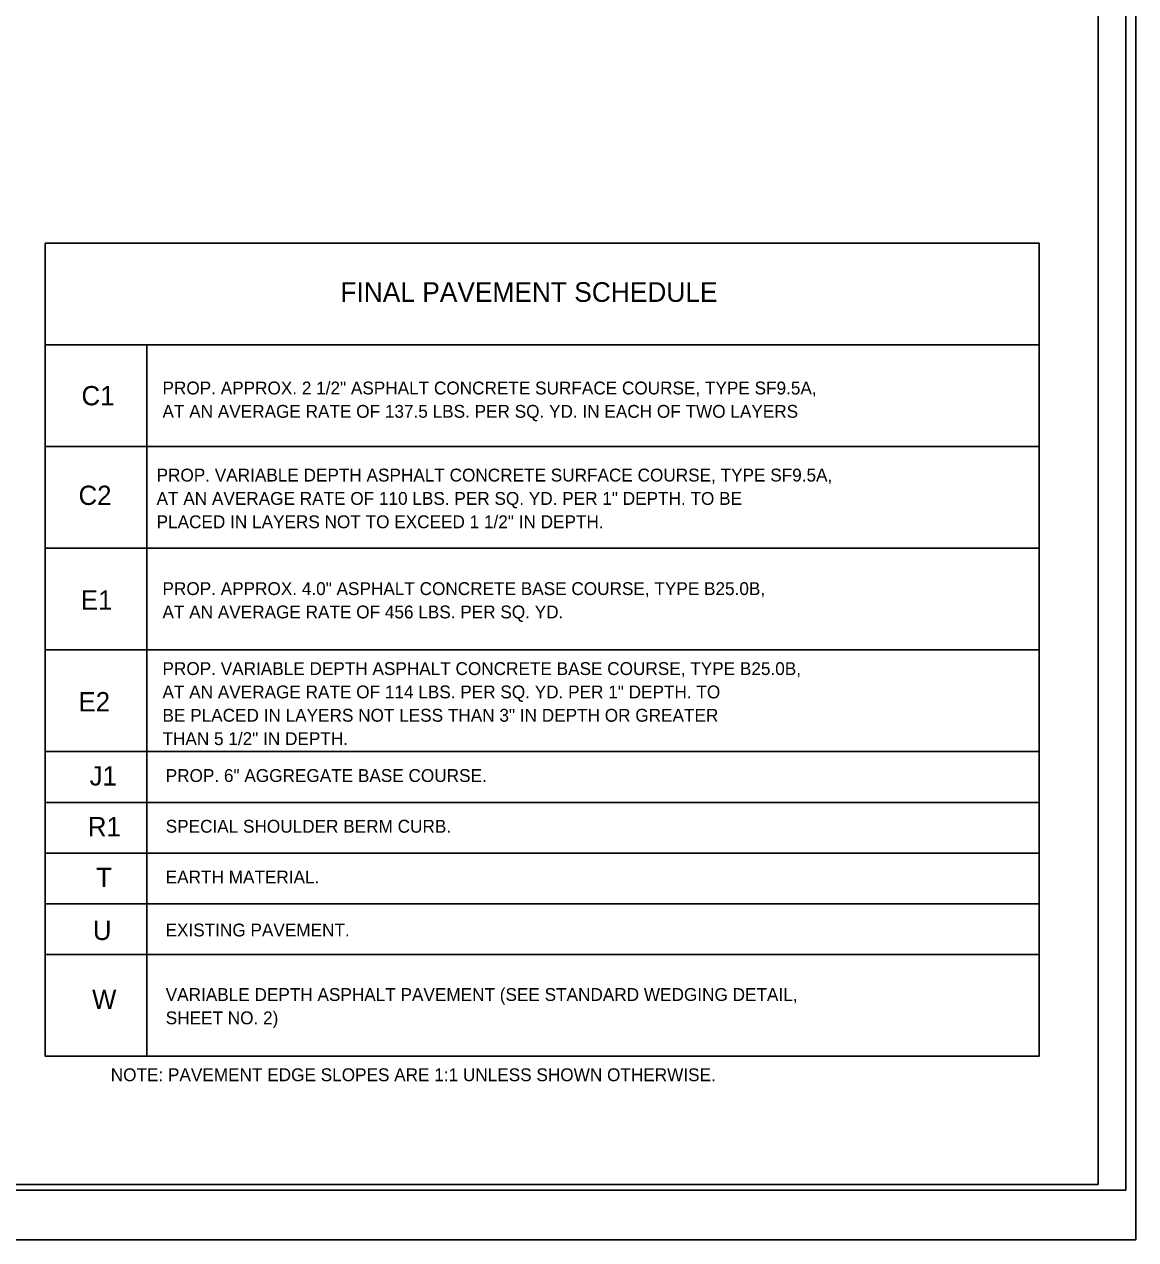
# Model space of a CAD drawing. Extents: x 1542177 to 1542464, y 45134 to 45344.
# Drawn here: x 1542320.47 to 1542360.73, y 45240.62 to 45284.62 of the extents above; entities that cross this region are included whole.
import ezdxf

# ---------------------------------------------------------------- set-up
doc = ezdxf.new("R2010")
doc.units = 0
for name, color, linetype in [('Default', 7, 'Continuous'), ('Sheet Cutting Line CELL', 7, 'Continuous'), ('Sheet Plot Border Inside CELL', 7, 'Continuous'), ('Sheet Plot Border Outside CELL', 7, 'Continuous'), ('Sheet Typical CELL', 7, 'Continuous')]:
    doc.layers.add(name, color=color, linetype=linetype)

msp = doc.modelspace()

# ---------------------------------------------------------------- linework, layer by layer
at = {"layer": 'Default'}
for p, q in [((1542324.908, 45249.102), (1542324.908, 45258.286)), ((1542321.274, 45248.12), (1542321.274, 45248.12))]:
    msp.add_line(p, q, dxfattribs=at)
for points in [[(1542321.226, 45276.696), (1542357.227, 45276.696), (1542357.227, 45273.014), (1542321.226, 45273.014)], [(1542321.226, 45258.286), (1542357.226, 45258.286), (1542357.226, 45256.449), (1542324.908, 45256.449), (1542321.226, 45256.449)], [(1542321.226, 45256.449), (1542357.226, 45256.449), (1542357.226, 45254.612), (1542324.908, 45254.612), (1542321.226, 45254.612)], [(1542321.226, 45254.612), (1542357.226, 45254.612), (1542357.226, 45252.775), (1542324.908, 45252.775), (1542321.226, 45252.775)], [(1542321.226, 45252.775), (1542357.226, 45252.775), (1542357.226, 45250.938), (1542324.908, 45250.938), (1542321.226, 45250.938)]]:
    msp.add_lwpolyline(points, close=True, dxfattribs=at)
for points in [[(1542324.908, 45269.331), (1542321.226, 45269.331), (1542321.226, 45273.014), (1542357.226, 45273.014), (1542357.226, 45269.331), (1542324.908, 45269.331), (1542324.908, 45273.014)], [(1542324.908, 45265.65), (1542321.226, 45265.65), (1542321.226, 45269.331), (1542357.226, 45269.331), (1542357.226, 45265.65), (1542324.908, 45265.65), (1542324.908, 45269.331)], [(1542324.908, 45261.968), (1542321.226, 45261.968), (1542321.226, 45265.65), (1542357.226, 45265.65), (1542357.226, 45261.968), (1542324.908, 45261.968), (1542324.908, 45265.65)], [(1542324.908, 45258.286), (1542321.226, 45258.286), (1542321.226, 45261.968), (1542357.226, 45261.968), (1542357.226, 45258.286), (1542324.908, 45258.286), (1542324.908, 45261.968)], [(1542324.908, 45247.257), (1542321.226, 45247.257), (1542321.226, 45250.938), (1542357.226, 45250.938), (1542357.226, 45247.257), (1542324.908, 45247.257), (1542324.908, 45250.938)]]:
    msp.add_lwpolyline(points, dxfattribs=at)
at = {"layer": 'Sheet Cutting Line CELL'}
msp.add_line((1542226.007, 45240.616), (1542360.727, 45240.616), dxfattribs=at)
at = {"layer": 'Sheet Plot Border Inside CELL'}
msp.add_lwpolyline([(1542360.367, 45326.82), (1542227.047, 45326.82), (1542227.047, 45242.412), (1542360.367, 45242.412)], close=True, dxfattribs=at)
at = {"layer": 'Sheet Plot Border Outside CELL'}
for points in [[(1542360.727, 45328.616), (1542226.007, 45328.616), (1542226.007, 45240.616), (1542360.727, 45240.616)], [(1542360.727, 45328.615), (1542226.007, 45328.615), (1542226.007, 45240.616), (1542360.727, 45240.616)]]:
    msp.add_lwpolyline(points, close=True, dxfattribs=at)
at = {"layer": 'Sheet Typical CELL'}
msp.add_lwpolyline([(1542359.367, 45326.616), (1542239.367, 45326.616), (1542239.367, 45242.616), (1542359.367, 45242.616)], close=True, dxfattribs=at)

# ---------------------------------------------------------------- texts
at = {"layer": 'Default'}
for s, height, p in [('FINAL PAVEMENT SCHEDULE', 0.7125, (1542331.919, 45274.567)), ('PROP. APPROX. 2 1/2" ASPHALT CONCRETE SURFACE COURSE, TYPE SF9.5A,', 0.46526, (1542325.473, 45271.216)), ('C1', 0.6982, (1542322.54, 45270.823)), ('AT AN AVERAGE RATE OF 137.5 LBS. PER SQ. YD. IN EACH OF TWO LAYERS', 0.46526, (1542325.473, 45270.371)), ('PROP. VARIABLE DEPTH ASPHALT CONCRETE SURFACE COURSE, TYPE SF9.5A,', 0.46526, (1542325.259, 45268.064)), ('C2', 0.6982, (1542322.433, 45267.216)), ('AT AN AVERAGE RATE OF 110 LBS. PER SQ. YD. PER 1" DEPTH. TO BE', 0.46526, (1542325.259, 45267.218)), ('PLACED IN LAYERS NOT TO EXCEED 1 1/2" IN DEPTH.', 0.46526, (1542325.259, 45266.373)), ('E1', 0.6982, (1542322.516, 45263.425)), ('PROP. APPROX. 4.0" ASPHALT CONCRETE BASE COURSE, TYPE B25.0B,', 0.46526, (1542325.473, 45263.953)), ('AT AN AVERAGE RATE OF 456 LBS. PER SQ. YD.', 0.46526, (1542325.473, 45263.108)), ('PROP. VARIABLE DEPTH ASPHALT CONCRETE BASE COURSE, TYPE B25.0B,', 0.46526, (1542325.473, 45261.058)), ('AT AN AVERAGE RATE OF 114 LBS. PER SQ. YD. PER 1" DEPTH. TO', 0.46526, (1542325.473, 45260.213)), ('E2', 0.6982, (1542322.433, 45259.743)), ('BE PLACED IN LAYERS NOT LESS THAN 3" IN DEPTH OR GREATER', 0.46526, (1542325.473, 45259.368)), ('THAN 5 1/2" IN DEPTH.', 0.46526, (1542325.473, 45258.522)), ('J1', 0.6982, (1542322.834, 45257.058)), ('PROP. 6" AGGREGATE BASE COURSE.', 0.46526, (1542325.59, 45257.186)), ('R1', 0.6982, (1542322.77, 45255.221)), ('SPECIAL SHOULDER BERM CURB.', 0.46526, (1542325.59, 45255.35)), ('T', 0.698, (1542323.07, 45253.384)), ('EARTH MATERIAL.', 0.46526, (1542325.59, 45253.513)), ('U', 0.698, (1542322.952, 45251.465)), ('EXISTING PAVEMENT.', 0.46526, (1542325.583, 45251.594)), ('W', 0.698, (1542322.923, 45248.971)), ('VARIABLE DEPTH ASPHALT PAVEMENT (SEE STANDARD WEDGING DETAIL,', 0.46526, (1542325.59, 45249.259)), ('SHEET NO. 2)', 0.46526, (1542325.59, 45248.414)), ('NOTE: PAVEMENT EDGE SLOPES ARE 1:1 UNLESS SHOWN OTHERWISE.', 0.46526, (1542323.598, 45246.354))]:
    msp.add_text(s, height=height, dxfattribs=at).set_placement(p)

doc.saveas('drawing.dxf')
